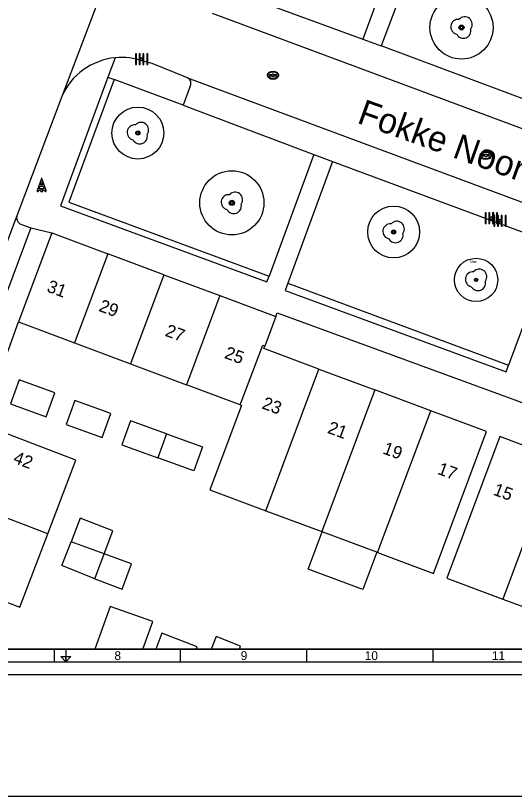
# Model space of a CAD drawing. Extents: x 192664 to 192925, y 446334 to 446521.
# Drawn here: x 192737.6 to 192777.1, y 446333.9 to 446395.7 of the extents above; entities that cross this region are included whole.
import ezdxf

# ---------------------------------------------------------------- set-up
doc = ezdxf.new("R2010")
doc.units = 0
for name, color, linetype in [('( Toegevoegd 29-11-2021 14_41_42) ondersteunend wegdeel vlak', 7, 'Continuous'), ('( Toegevoegd 29-11-2021 14_41_42) wegdeel vlak', 7, 'Continuous'), ('1010 viewport', 7, 'Continuous'), ('B-GV-GR-BOOM-S', 7, 'Continuous'), ('boom', 7, 'Continuous'), ('bovenleidingmast', 7, 'Continuous'), ('grens niveau plus 1', 7, 'Continuous'), ('huisnummerreeks BGT', 7, 'Continuous'), ('inspectie-   rioolput', 7, 'Continuous'), ('kant verharding', 7, 'Continuous'), ('kolk', 7, 'Continuous'), ('Luifel', 7, 'Continuous'), ('pand op maaiveld vlak', 7, 'Continuous'), ('straatnaam', 7, 'Continuous'), ('TEKST', 7, 'Continuous'), ('verkeerseiland - berm', 7, 'Continuous'), ('X-XX-AL-TEKENBLAD-S', 7, 'Continuous'), ('X-XX-AL-TEKENBLAD_KADER-G', 7, 'Continuous')]:
    doc.layers.add(name, color=color, linetype=linetype)

msp = doc.modelspace()

# ---------------------------------------------------------------- linework, layer by layer
at = {"layer": '( Toegevoegd 29-11-2021 14_41_42) ondersteunend wegdeel vlak'}
for p, q in [((192745.467, 446392.368), (192744.875, 446390.822)), ((192744.875, 446390.822), (192745.382, 446390.635)), ((192751.408, 446390.132), (192750.855, 446388.618))]:
    msp.add_line(p, q, dxfattribs=at)
msp.add_lwpolyline([(192751.186, 446390.775), (192748.395, 446391.902), (192747.677, 446392.092)], dxfattribs=at)
for centre, radius, start, end in [((192745.949, 446387.244), 5.146, 70.38453, 95.3782), ((192750.999, 446390.351), 0.464, 331.87737, 66.21777)]:
    msp.add_arc(centre, radius, start, end, dxfattribs=at)
at = {"layer": '( Toegevoegd 29-11-2021 14_41_42) wegdeel vlak'}
for p, q in [((192741.229, 446389.304), (192737.657, 446379.855)), ((192738.766, 446378.901), (192740.444, 446378.51)), ((192734.872, 446363.349), (192737.803, 446371.456))]:
    msp.add_line(p, q, dxfattribs=at)
for points in [[(192744.875, 446390.822), (192741.123, 446380.652), (192757.478, 446374.617), (192757.644, 446375.067)], [(192759.13, 446374.517), (192758.916, 446373.935), (192776.422, 446367.504), (192776.611, 446368.02)], [(192758.17, 446371.875), (192758.285, 446372.185), (192775.949, 446365.705), (192777.106, 446365.279), (192794.631, 446358.595), (192794.529, 446358.306)]]:
    msp.add_lwpolyline(points, dxfattribs=at)
msp.add_arc((192745.947, 446387.241), 5.149, 95.34868, 156.38386, dxfattribs=at)
at = {"layer": '1010 viewport'}
msp.add_lwpolyline([(192675.743, 446509.756), (192860.643, 446509.756), (192860.643, 446345.556), (192675.743, 446345.556)], close=True, dxfattribs=at)
at = {"layer": 'B-GV-GR-BOOM-S'}
for centre, radius in [((192772.885, 446394.761), 2.5), ((192772.885, 446394.761), 0.2), ((192747.256, 446386.406), 2.054), ((192747.256, 446386.406), 0.164), ((192754.7, 446380.881), 2.539), ((192754.7, 446380.881), 0.203), ((192767.508, 446378.575), 2.054), ((192767.508, 446378.575), 0.164), ((192774.039, 446374.78), 1.713), ((192774.039, 446374.78), 0.137)]:
    msp.add_circle(centre, radius, dxfattribs=at)
at = {"layer": 'boom'}
for centre in [(192772.885, 446394.761), (192747.256, 446386.406), (192754.7, 446380.881), (192767.508, 446378.575), (192774.039, 446374.78)]:
    msp.add_circle(centre, 0.1, dxfattribs=at)
for centre, radius, start, end in [((192773.135, 446395.011), 0.6, 323.54458, 138.4658), ((192772.635, 446394.811), 0.6, 85.13702, 257.75442), ((192772.885, 446394.761), 0.1, 0, 180), ((192773.035, 446394.511), 0.6, 208.50578, 13.83556), ((192772.885, 446394.761), 0.1, 180, 0), ((192747.006, 446386.456), 0.6, 85.13702, 257.75442), ((192747.506, 446386.656), 0.6, 323.54458, 138.4658), ((192747.406, 446386.156), 0.6, 208.50578, 13.83556), ((192747.256, 446386.406), 0.1, 0, 180), ((192747.256, 446386.406), 0.1, 180, 0), ((192754.45, 446380.931), 0.6, 85.13702, 257.75442), ((192754.95, 446381.131), 0.6, 323.54458, 138.4658), ((192754.85, 446380.631), 0.6, 208.50578, 13.83556), ((192754.7, 446380.881), 0.1, 0, 180), ((192754.7, 446380.881), 0.1, 180, 0), ((192767.758, 446378.825), 0.6, 323.54458, 138.4658), ((192767.258, 446378.625), 0.6, 85.13702, 257.75442), ((192767.658, 446378.325), 0.6, 208.50578, 13.83556), ((192767.508, 446378.575), 0.1, 0, 180), ((192767.508, 446378.575), 0.1, 180, 0), ((192773.789, 446374.83), 0.6, 85.13702, 257.75442), ((192774.289, 446375.03), 0.6, 323.54458, 138.4658), ((192774.189, 446374.53), 0.6, 208.50578, 13.83556), ((192774.039, 446374.78), 0.1, 0, 180), ((192774.039, 446374.78), 0.1, 180, 0)]:
    msp.add_arc(centre, radius, start, end, dxfattribs=at)
at = {"layer": 'bovenleidingmast'}
for p, q in [((192739.623, 446382.82), (192739.282, 446381.847)), ((192739.982, 446381.847), (192739.641, 446382.82))]:
    msp.add_line(p, q, dxfattribs=at)
for points in [[(192739.641, 446382.517), (192739.719, 446382.297), (192739.545, 446382.297), (192739.623, 446382.517)], [(192739.376, 446381.814), (192739.405, 446381.897), (192739.545, 446381.897)], [(192739.719, 446381.897), (192739.859, 446381.897), (192739.888, 446381.814)]]:
    msp.add_lwpolyline(points, dxfattribs=at)
msp.add_lwpolyline([(192739.754, 446382.197), (192739.824, 446381.997), (192739.44, 446381.997), (192739.51, 446382.197)], close=True, dxfattribs=at)
for centre, radius, start, end in [((192739.632, 446382.817), 0.01, 19.29005, 160.70995), ((192739.632, 446382.514), 0.01, 19.29005, 160.70995), ((192739.329, 446381.83), 0.05, 160.70995, 340.70995), ((192739.632, 446381.847), 0.1, 0, 180), ((192739.632, 446381.847), 0.1, 180, 0), ((192739.632, 446381.847), 0.1, 30, 150), ((192739.935, 446381.83), 0.05, 199.29005, 19.29005)]:
    msp.add_arc(centre, radius, start, end, dxfattribs=at)
at = {"layer": 'grens niveau plus 1'}
msp.add_line((192745.049, 446348.922), (192743.84, 446345.556), dxfattribs=at)
msp.add_lwpolyline([(192747.65, 446345.556), (192748.43, 446347.726), (192745.049, 446348.922)], dxfattribs=at)
at = {"layer": 'inspectie-   rioolput'}
for p, q in [((192757.865, 446391.023), (192757.708, 446391.023)), ((192757.708, 446390.948), (192757.865, 446390.948)), ((192758.208, 446391.023), (192758.051, 446391.023)), ((192758.051, 446390.948), (192758.208, 446390.948)), ((192774.715, 446384.675), (192774.558, 446384.675)), ((192774.558, 446384.6), (192774.715, 446384.6)), ((192775.058, 446384.675), (192774.901, 446384.675)), ((192774.901, 446384.6), (192775.058, 446384.6))]:
    msp.add_line(p, q, dxfattribs=at)
for centre, radius, start, end in [((192757.708, 446390.985), 0.0375, 90, 270), ((192757.958, 446390.985), 0.1, 0, 180), ((192757.958, 446390.985), 0.1, 157.97569, 180), ((192757.958, 446390.985), 0.1, 180, 202.02431), ((192757.958, 446390.985), 0.1, 180, 0), ((192757.958, 446390.985), 0.1, 0, 22.02431), ((192757.958, 446390.985), 0.1, 337.97569, 0), ((192758.208, 446390.985), 0.0375, 270, 90), ((192774.558, 446384.637), 0.0375, 90, 270), ((192774.808, 446384.637), 0.1, 0, 180), ((192774.808, 446384.637), 0.1, 157.97569, 180), ((192774.808, 446384.637), 0.1, 180, 202.02431), ((192774.808, 446384.637), 0.1, 180, 0), ((192774.808, 446384.637), 0.1, 0, 22.02431), ((192774.808, 446384.637), 0.1, 337.97569, 0), ((192775.058, 446384.637), 0.0375, 270, 90)]:
    msp.add_arc(centre, radius, start, end, dxfattribs=at)
for centre, major_axis, ratio in [((192757.958, 446390.985), (-0.442, 0), 0.73911), ((192757.958, 446390.985), (-0.392, 0), 0.689655), ((192774.808, 446384.637), (-0.442, 0), 0.73911), ((192774.808, 446384.637), (-0.392, 0), 0.689655)]:
    msp.add_ellipse(centre, major_axis=major_axis, ratio=ratio, dxfattribs=at)
at = {"layer": 'kant verharding'}
for p, q in [((192746.655, 446403.591), (192741.229, 446389.304)), ((192753.133, 446395.89), (192813.567, 446373.412)), ((192765.07, 446393.833), (192766.521, 446393.307)), ((192751.186, 446390.775), (192811.557, 446368.364)), ((192761.203, 446384.713), (192762.674, 446384.166)), ((192737.657, 446379.855), (192731.919, 446364.598)), ((192737.908, 446379.221), (192738.766, 446378.901))]:
    msp.add_line(p, q, dxfattribs=at)
msp.add_lwpolyline([(192738.766, 446378.901), (192733.402, 446364.531), (192732.55, 446364.886)], dxfattribs=at)
msp.add_arc((192738.238, 446379.719), 0.597, 166.79061, 236.40652, dxfattribs=at)
at = {"layer": 'kolk'}
for points in [[(192747.144, 446392.252), (192747.144, 446392.677), (192747.059, 446392.677), (192747.059, 446392.252), (192747.059, 446391.827), (192747.144, 446391.827)], [(192747.442, 446392.252), (192747.442, 446392.677), (192747.357, 446392.677), (192747.357, 446392.252), (192747.357, 446391.827), (192747.442, 446391.827)], [(192747.739, 446392.252), (192747.739, 446392.677), (192747.654, 446392.677), (192747.654, 446392.252), (192747.654, 446391.827), (192747.739, 446391.827)], [(192748.037, 446392.252), (192748.037, 446392.677), (192747.952, 446392.677), (192747.952, 446392.252), (192747.952, 446391.827), (192748.037, 446391.827)], [(192774.842, 446379.663), (192774.842, 446380.088), (192774.757, 446380.088), (192774.757, 446379.663), (192774.757, 446379.238), (192774.842, 446379.238)], [(192775.14, 446379.663), (192775.14, 446380.088), (192775.055, 446380.088), (192775.055, 446379.663), (192775.055, 446379.238), (192775.14, 446379.238)], [(192775.437, 446379.663), (192775.437, 446380.088), (192775.352, 446380.088), (192775.352, 446379.663), (192775.352, 446379.238), (192775.437, 446379.238)], [(192775.735, 446379.663), (192775.735, 446380.088), (192775.65, 446380.088), (192775.65, 446379.663), (192775.65, 446379.238), (192775.735, 446379.238)], [(192775.521, 446379.454), (192775.521, 446379.879), (192775.436, 446379.879), (192775.436, 446379.454), (192775.436, 446379.029), (192775.521, 446379.029)], [(192775.819, 446379.454), (192775.819, 446379.879), (192775.734, 446379.879), (192775.734, 446379.454), (192775.734, 446379.029), (192775.819, 446379.029)], [(192776.116, 446379.454), (192776.116, 446379.879), (192776.031, 446379.879), (192776.031, 446379.454), (192776.031, 446379.029), (192776.116, 446379.029)], [(192776.414, 446379.454), (192776.414, 446379.879), (192776.329, 446379.879), (192776.329, 446379.454), (192776.329, 446379.029), (192776.414, 446379.029)]]:
    msp.add_lwpolyline(points, close=True, dxfattribs=at)
for centre, start, end in [((192747.548, 446392.252), 0, 180), ((192747.548, 446392.252), 180, 0), ((192775.246, 446379.663), 0, 180), ((192775.246, 446379.663), 180, 0), ((192775.925, 446379.454), 0, 180), ((192775.925, 446379.454), 180, 0)]:
    msp.add_arc(centre, 0.1, start, end, dxfattribs=at)
at = {"layer": 'Luifel'}
for points in [[(192766.166, 446353.222), (192765.058, 446350.263), (192760.747, 446351.877), (192761.855, 446354.836)], [(192743.852, 446351.105), (192746.012, 446350.305), (192746.753, 446352.307), (192744.593, 446353.107)]]:
    msp.add_lwpolyline(points, dxfattribs=at)
at = {"layer": 'pand op maaiveld vlak'}
for p, q in [((192740.444, 446378.51), (192737.803, 446371.456)), ((192740.444, 446378.51), (192744.876, 446376.852)), ((192744.876, 446376.852), (192742.235, 446369.796)), ((192749.307, 446375.193), (192744.876, 446376.852)), ((192749.307, 446375.193), (192746.666, 446368.138)), ((192749.307, 446375.193), (192753.739, 446373.534)), ((192753.739, 446373.534), (192751.098, 446366.48)), ((192753.739, 446373.534), (192758.17, 446371.875)), ((192737.803, 446371.456), (192742.235, 446369.796)), ((192758.17, 446371.875), (192757.312, 446369.547)), ((192742.235, 446369.796), (192746.666, 446368.138)), ((192746.666, 446368.138), (192751.098, 446366.48)), ((192757.388, 446356.507), (192761.585, 446367.723)), ((192761.585, 446367.723), (192766.014, 446366.072)), ((192755.366, 446364.882), (192751.098, 446366.48)), ((192766.014, 446366.072), (192761.814, 446354.851)), ((192770.443, 446364.421), (192766.014, 446366.072)), ((192766.241, 446353.194), (192770.443, 446364.421)), ((192749.523, 446362.586), (192748.837, 446360.686)), ((192780.333, 446360.728), (192776.152, 446349.513)), ((192740.119, 446354.688), (192732.657, 446357.527)), ((192757.388, 446356.507), (192761.814, 446354.851)), ((192761.855, 446354.836), (192761.814, 446354.851)), ((192766.166, 446353.222), (192761.855, 446354.836)), ((192744.593, 446353.107), (192741.961, 446354.044)), ((192743.852, 446351.105), (192744.593, 446353.107)), ((192766.241, 446353.194), (192766.166, 446353.222)), ((192776.152, 446349.513), (192780.57, 446347.867)), ((192749.154, 446346.827), (192748.671, 446345.556)), ((192755.301, 446345.556), (192755.392, 446345.788))]:
    msp.add_line(p, q, dxfattribs=at)
for points in [[(192755.366, 446364.882), (192757.145, 446369.61), (192757.312, 446369.547)], [(192761.585, 446367.723), (192757.237, 446369.345), (192757.312, 446369.547)], [(192737.844, 446366.858), (192737.159, 446364.958), (192740, 446363.934), (192740.685, 446365.834), (192737.844, 446366.858)], [(192742.273, 446365.238), (192741.579, 446363.341), (192744.415, 446362.304), (192745.109, 446364.201), (192742.273, 446365.238)], [(192755.366, 446364.882), (192755.462, 446364.846), (192752.961, 446358.164), (192757.388, 446356.507)], [(192766.241, 446353.194), (192770.667, 446351.537), (192774.871, 446362.77), (192770.443, 446364.421)], [(192740.119, 446354.688), (192742.334, 446360.51), (192734.872, 446363.349)], [(192749.523, 446362.586), (192746.682, 446363.612), (192745.996, 446361.712), (192748.837, 446360.686)], [(192749.523, 446362.586), (192752.364, 446361.56), (192751.678, 446359.66), (192748.837, 446360.686)], [(192780.333, 446360.728), (192775.916, 446362.375), (192771.735, 446351.16), (192776.152, 446349.513)], [(192744.593, 446353.107), (192745.266, 446354.926), (192742.68, 446355.914), (192741.961, 446354.044)], [(192730.442, 446351.705), (192737.904, 446348.866), (192740.119, 446354.688)], [(192743.852, 446351.105), (192741.241, 446352.173), (192741.961, 446354.044)], [(192751.883, 446345.556), (192751.953, 446345.74), (192749.154, 446346.827)], [(192755.392, 446345.788), (192753.448, 446346.547), (192753.05, 446345.556)]]:
    msp.add_lwpolyline(points, dxfattribs=at)
at = {"layer": 'verkeerseiland - berm'}
for p, q in [((192768.471, 446403.091), (192765.07, 446393.833)), ((192770.009, 446402.51), (192766.521, 446393.307)), ((192754.334, 446397.778), (192765.07, 446393.833)), ((192783.608, 446386.92), (192766.521, 446393.307)), ((192750.855, 446388.618), (192745.382, 446390.635)), ((192750.855, 446388.618), (192761.203, 446384.713)), ((192761.203, 446384.713), (192757.644, 446375.067)), ((192762.674, 446384.166), (192759.13, 446374.517)), ((192762.674, 446384.166), (192780.156, 446377.668)), ((192780.156, 446377.668), (192776.611, 446368.02)), ((192759.13, 446374.517), (192776.611, 446368.02))]:
    msp.add_line(p, q, dxfattribs=at)
msp.add_lwpolyline([(192745.382, 446390.635), (192741.79, 446380.939), (192757.644, 446375.067)], dxfattribs=at)
at = {"layer": 'X-XX-AL-TEKENBLAD-S'}
for p, q in [((192740.643, 446344.556), (192740.643, 446345.556)), ((192741.543, 446345.556), (192741.543, 446344.556)), ((192750.643, 446344.556), (192750.643, 446345.556)), ((192760.643, 446344.556), (192760.643, 446345.556)), ((192770.643, 446344.556), (192770.643, 446345.556)), ((192741.543, 446344.956), (192741.543, 446344.556)), ((192741.543, 446344.556), (192741.543, 446344.956)), ((192674.743, 446344.556), (192908.543, 446344.556)), ((192671.743, 446343.556), (192909.543, 446343.556))]:
    msp.add_line(p, q, dxfattribs=at)
msp.add_lwpolyline([(192675.743, 446345.556), (192907.543, 446345.556), (192907.543, 446509.756), (192675.743, 446509.756)], close=True, dxfattribs=at)
for points in [[(192741.543, 446344.556), (192741.143, 446344.956), (192741.543, 446344.956)], [(192741.543, 446344.956), (192741.943, 446344.956), (192741.543, 446344.556)]]:
    msp.add_lwpolyline(points, dxfattribs=at)
at = {"layer": 'X-XX-AL-TEKENBLAD_KADER-G'}
msp.add_lwpolyline([(192664.22, 446520.974), (192925.029, 446520.974), (192925.029, 446333.894), (192664.22, 446333.894)], close=True, dxfattribs=at)

# ---------------------------------------------------------------- texts
at = {"layer": 'huisnummerreeks BGT'}
for s, rotation, p in [('31', 339.5, (192739.979, 446373.88)), ('29', 339.5, (192744.094, 446372.34)), ('27', 339.5, (192749.348, 446370.373)), ('25', 339.5, (192754.039, 446368.617)), ('23', 339.6, (192757.013, 446364.626)), ('21', 339.6, (192762.203, 446362.69)), ('19', 339.6, (192766.578, 446361.059)), ('42', 339.2, (192737.312, 446360.322)), ('17', 339.6, (192770.915, 446359.442)), ('15', 339.6, (192775.323, 446357.793))]:
    msp.add_text(s, height=1, rotation=rotation, dxfattribs=at).set_placement(p)
at = {"layer": 'straatnaam'}
msp.add_text('Fokke Noordhoffstraat', height=2, rotation=340.2, dxfattribs=at).set_placement((192764.533, 446387.236))
at = {"layer": 'TEKST'}
msp.add_text('Mak', height=0.2, dxfattribs=at).set_placement((192773.569, 446376.121))
at = {"layer": 'X-XX-AL-TEKENBLAD-S'}
for s, p in [('8', (192745.399, 446344.685)), ('9', (192755.399, 446344.685)), ('10', (192765.224, 446344.685)), ('11', (192775.293, 446344.685))]:
    msp.add_text(s, height=0.7, dxfattribs=at).set_placement(p)

doc.saveas('drawing.dxf')
